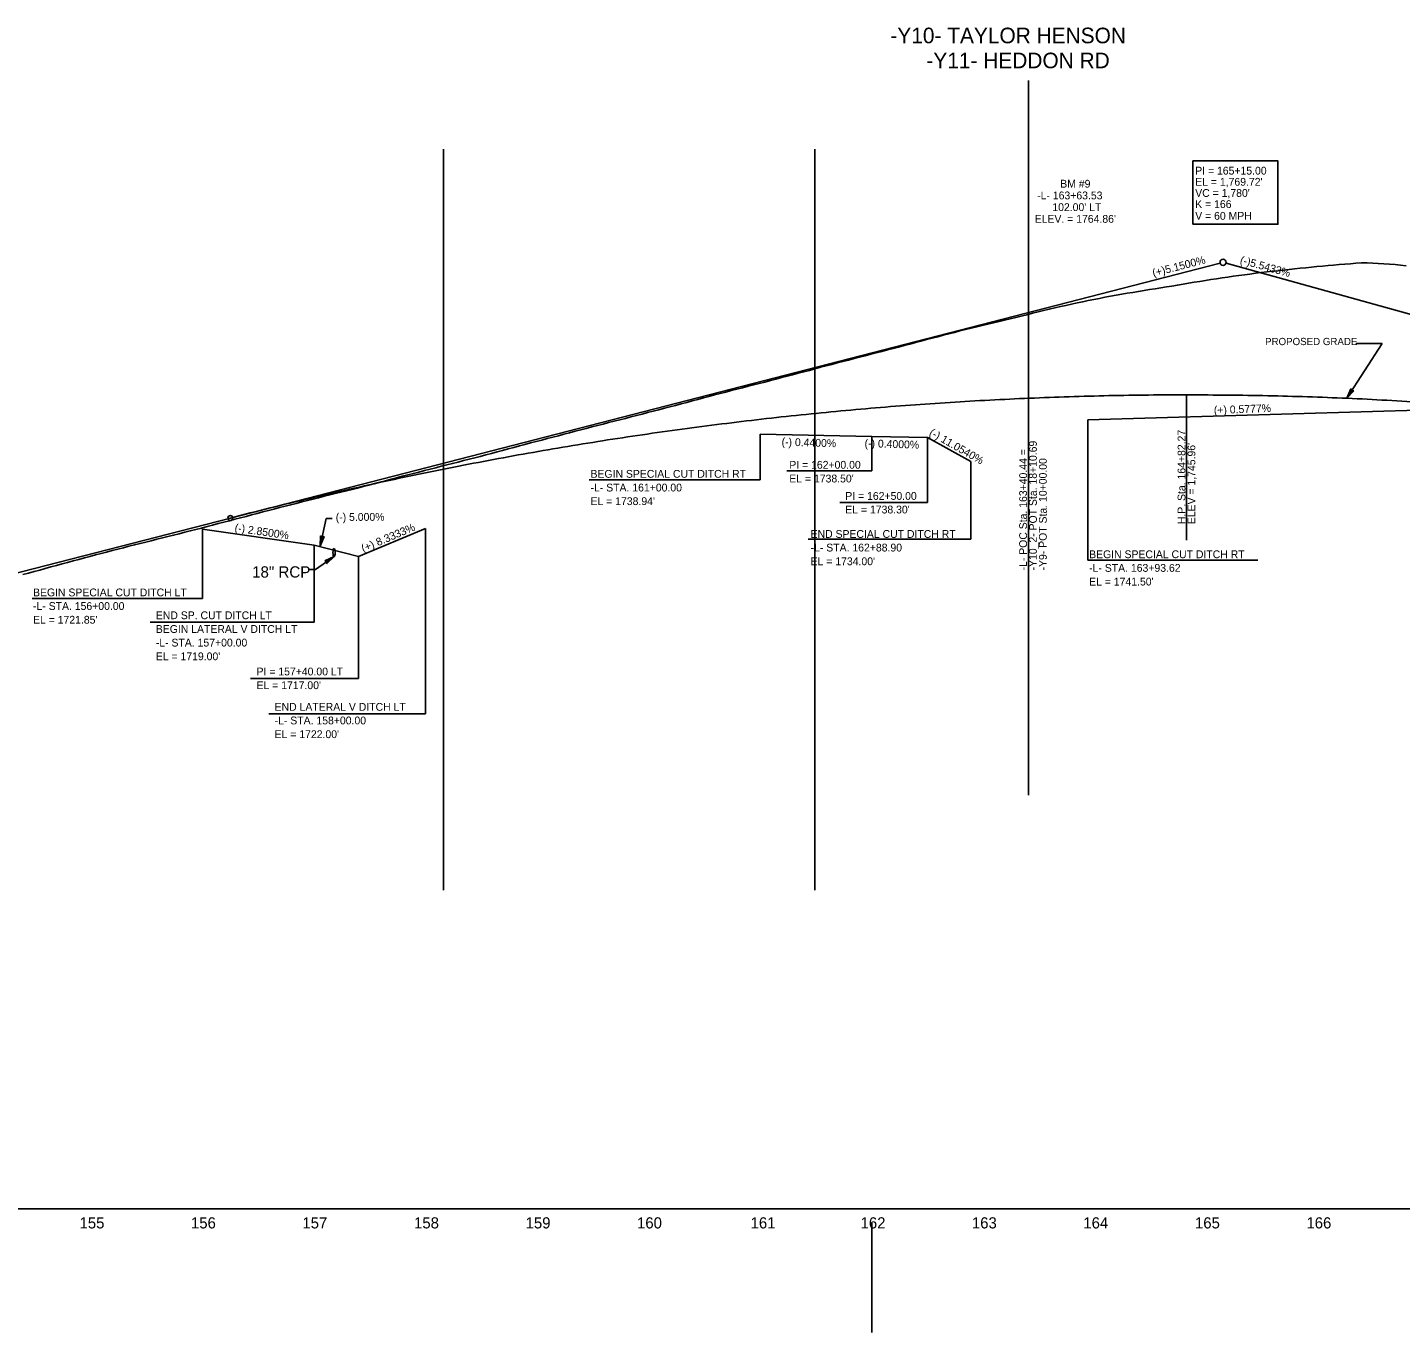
# Model space of a CAD drawing. Extents: x 498575 to 532350, y 405181 to 484585.
# Drawn here: x 520262 to 521493, y 483123 to 484293 of the extents above; entities that cross this region are included whole.
import ezdxf

# ---------------------------------------------------------------- set-up
doc = ezdxf.new("R2010")
doc.units = 0
for name, color, linetype in [('Exist Profile Cell', 7, 'Continuous'), ('Exist Vertical Profile Ground Line', 7, 'Continuous'), ('Exist Vertical Profile Horizontal Axis Label Major', 7, 'Continuous'), ('Prop Drainage Structure Pipe Welded Steel 54in Label', 7, 'Continuous'), ('Prop Grid Mask', 7, 'Continuous'), ('Prop PFL Text', 7, 'Continuous'), ('Prop Vertical Profile Curve Label', 7, 'Continuous'), ('Prop Vertical Profile Ditch Grade Left', 7, 'Continuous'), ('Prop Vertical Profile Ditch Grade Left Label', 7, 'Continuous'), ('Prop Vertical Profile Ditch Grade Right', 7, 'Continuous'), ('Prop Vertical Profile Ditch Grade Right Label', 7, 'Continuous'), ('Prop Vertical Profile Grade', 7, 'Continuous'), ('Prop Vertical Profile Grade Label', 7, 'Continuous'), ('Prop Vertical Profile Strip Grade', 7, 'Continuous'), ('Prop VPI Label', 7, 'Continuous'), ('Scratch_Level_2', 7, 'Continuous'), ('Scratch_Level_4', 7, 'Continuous'), ('Sheet Profile Grid Minor CELL', 7, 'Continuous')]:
    doc.layers.add(name, color=color, linetype=linetype)

msp = doc.modelspace()

# ---------------------------------------------------------------- linework, layer by layer
at = {"layer": 'Exist Profile Cell'}
msp.add_line((505856.7, 483233.7), (526056.7, 483233.7), dxfattribs=at)
at = {"layer": 'Exist Vertical Profile Ground Line'}
for points in [[(521313.2, 484065.2), (521318.2, 484066), (521323.2, 484066.9), (521328.2, 484067.6), (521333.2, 484068.4), (521338.2, 484069.1), (521343.2, 484069.8), (521348.2, 484070.4), (521353.2, 484071.1), (521358.2, 484071.8), (521363.2, 484072.5), (521368.2, 484073.1), (521373.2, 484073.7), (521378.2, 484074.3), (521383.2, 484074.8), (521388.2, 484075.3), (521393.2, 484075.9), (521398.2, 484076.5), (521403.2, 484077), (521408.2, 484077.5), (521413.2, 484078.1), (521418.2, 484078.6), (521423.2, 484079), (521428.2, 484079.5), (521433.2, 484079.9), (521438.2, 484080.4), (521443.2, 484080.8), (521448.2, 484081.1), (521453.2, 484081.5), (521458.2, 484081.8), (521463.2, 484081.8), (521468.2, 484081.6), (521473.2, 484081.4), (521478.2, 484081), (521483.2, 484080.7), (521488.2, 484080.3), (521493.2, 484079.8), (521498.2, 484079.3)], [(520813.2, 483946.3), (520818.2, 483947.6), (520823.2, 483948.8), (520828.2, 483950.1), (520833.2, 483951.5), (520838.2, 483952.8), (520843.2, 483954.1), (520848.2, 483955.4), (520853.2, 483956.8), (520858.2, 483958.1), (520863.2, 483959.5), (520868.2, 483960.8), (520873.2, 483962.1), (520878.2, 483963.4), (520883.2, 483964.7), (520888.2, 483966), (520893.2, 483967.3), (520898.2, 483968.6), (520903.2, 483969.9), (520908.2, 483971.2), (520913.2, 483972.4), (520918.2, 483973.7), (520923.2, 483975), (520928.2, 483976.4), (520933.2, 483977.7), (520938.2, 483979), (520943.2, 483980.3), (520948.2, 483981.6), (520953.2, 483982.9), (520958.2, 483984.2), (520963.2, 483985.5), (520968.2, 483986.8), (520973.2, 483988.2), (520978.2, 483989.5), (520983.2, 483990.8), (520988.2, 483992.1), (520993.2, 483993.4), (520998.2, 483994.7), (521003.2, 483996), (521008.2, 483997.3), (521013.2, 483998.5), (521018.2, 483999.9), (521023.2, 484001.2), (521028.2, 484002.5), (521033.2, 484003.8), (521038.2, 484005.1), (521043.2, 484006.4), (521048.2, 484007.7), (521053.2, 484009.1), (521058.2, 484010.4), (521063.2, 484011.7), (521068.2, 484013), (521073.2, 484014.3), (521078.2, 484015.6), (521083.2, 484017), (521088.2, 484018.2), (521093.2, 484019.5), (521098.2, 484020.8), (521103.2, 484022), (521108.2, 484023.2), (521113.2, 484024.5), (521118.2, 484025.7), (521123.2, 484026.9), (521128.2, 484028.1), (521133.2, 484029.3), (521138.2, 484030.5), (521143.2, 484031.8), (521148.2, 484033), (521153.2, 484034.2), (521158.2, 484035.4), (521163.2, 484036.7), (521168.2, 484037.9), (521173.2, 484039.2), (521178.2, 484040.3), (521183.2, 484041.5), (521188.2, 484042.6), (521193.2, 484043.7), (521198.2, 484044.8), (521203.2, 484045.9), (521208.2, 484047), (521213.2, 484048), (521218.2, 484049), (521223.2, 484050), (521228.2, 484051), (521233.2, 484051.9), (521238.2, 484052.8), (521243.2, 484053.7), (521248.2, 484054.6), (521253.2, 484055.4), (521258.2, 484056.3), (521263.2, 484057.1), (521268.2, 484057.9), (521273.2, 484058.7), (521278.2, 484059.5), (521283.2, 484060.3), (521288.2, 484061.1), (521293.2, 484062), (521298.2, 484062.8), (521303.2, 484063.6), (521308.2, 484064.4), (521313.2, 484065.2)], [(520313.2, 483817.3), (520318.2, 483818.7), (520323.2, 483820), (520328.2, 483821.3), (520333.2, 483822.6), (520338.2, 483823.9), (520343.2, 483825.2), (520348.2, 483826.5), (520353.2, 483827.8), (520358.2, 483829), (520363.2, 483830.3), (520368.2, 483831.5), (520373.2, 483832.7), (520378.2, 483834), (520383.2, 483835.2), (520388.2, 483836.5), (520393.2, 483837.7), (520398.2, 483839), (520403.2, 483840.3), (520408.2, 483841.5), (520413.2, 483842.8), (520418.2, 483844.1), (520423.2, 483845.4), (520428.2, 483846.8), (520433.2, 483848.1), (520438.2, 483849.4), (520443.2, 483850.7), (520448.2, 483852), (520453.2, 483853.3), (520458.2, 483854.6), (520463.2, 483855.9), (520468.2, 483857.2), (520473.2, 483858.5), (520478.2, 483859.8), (520483.2, 483861.1), (520488.2, 483862.4), (520493.2, 483863.7), (520498.2, 483865), (520503.2, 483866.2), (520508.2, 483867.5), (520513.2, 483868.8), (520518.2, 483870), (520523.2, 483871.3), (520528.2, 483872.6), (520533.2, 483873.8), (520538.2, 483875.1), (520543.2, 483876.3), (520548.2, 483877.5), (520553.2, 483878.8), (520558.2, 483880), (520563.2, 483881.3), (520568.2, 483882.5), (520573.2, 483883.9), (520578.2, 483885.2), (520583.2, 483886.5), (520588.2, 483887.9), (520593.2, 483889.2), (520598.2, 483890.5), (520603.2, 483891.8), (520608.2, 483893.1), (520613.2, 483894.3), (520618.2, 483895.6), (520623.2, 483896.9), (520628.2, 483898.2), (520633.2, 483899.5), (520638.2, 483900.8), (520643.2, 483902.1), (520648.2, 483903.3), (520653.2, 483904.6), (520658.2, 483905.9), (520663.2, 483907.1), (520668.2, 483908.4), (520673.2, 483909.7), (520678.2, 483911), (520683.2, 483912.4), (520688.2, 483913.7), (520693.2, 483915.1), (520698.2, 483916.4), (520703.2, 483917.8), (520708.2, 483919.1), (520713.2, 483920.4), (520718.2, 483921.6), (520723.2, 483922.9), (520728.2, 483924.3), (520733.2, 483925.6), (520738.2, 483926.9), (520743.2, 483928.2), (520748.2, 483929.5), (520753.2, 483930.9), (520758.2, 483932.2), (520763.2, 483933.5), (520768.2, 483934.8), (520773.2, 483936), (520778.2, 483937.3), (520783.2, 483938.6), (520788.2, 483939.9), (520793.2, 483941.1), (520798.2, 483942.4), (520803.2, 483943.7), (520808.2, 483945), (520813.2, 483946.3)], [(520258.2, 483802.5), (520263.2, 483803.8), (520268.2, 483805.1), (520273.2, 483806.5), (520278.2, 483807.8), (520283.2, 483809.2), (520288.2, 483810.6), (520293.2, 483811.9), (520298.2, 483813.3), (520303.2, 483814.7), (520308.2, 483816), (520313.2, 483817.3)]]:
    msp.add_lwpolyline(points, dxfattribs=at)
at = {"layer": 'Prop Drainage Structure Pipe Welded Steel 54in Label'}
for p in [(520537.1, 483818.7), (520514.3, 483806.9)]:
    msp.add_line(p, (520520.3, 483806.9), dxfattribs=at)
msp.add_lwpolyline([(520528.8, 483814.8), (520537.1, 483818.7), (520530.6, 483812.2), (520530.6, 483814.2)], close=True, dxfattribs=at)
msp.add_ellipse((520537.1, 483822.2), major_axis=(0, 3.5), ratio=0.285714, dxfattribs=at)
at = {"layer": 'Prop Grid Mask'}
msp.add_lwpolyline([(521307, 484116.4), (521383.2, 484116.4), (521383.2, 484173.2), (521307, 484173.2)], close=True, dxfattribs=at)
at = {"layer": 'Prop PFL Text'}
for p, q in [((521445.1, 483960.4), (521476.6, 484009.6)), ((521476.6, 484009.6), (521453.2, 484009.6))]:
    msp.add_line(p, q, dxfattribs=at)
msp.add_lwpolyline([(521451.2, 483967.2), (521445.1, 483960.4), (521448.6, 483968.9), (521449.3, 483967.1)], close=True, dxfattribs=at)
at = {"layer": 'Prop Vertical Profile Curve Label'}
msp.add_circle((520444.1, 483853.1), 2.25, dxfattribs=at)
at = {"layer": 'Prop Vertical Profile Ditch Grade Left'}
msp.add_lwpolyline([(520419.1, 483843), (520519.1, 483828.7), (520559.1, 483818.7), (520619.1, 483843.7), (520619.1, 483843.7)], dxfattribs=at)
at = {"layer": 'Prop Vertical Profile Ditch Grade Left Label'}
for p, q in [((520529.9, 483852.6), (520524.6, 483828)), ((520529.9, 483852.6), (520535.4, 483852.6)), ((520419.1, 483843), (520419.1, 483780.9)), ((520619.1, 483843.7), (520619.1, 483677.6)), ((520519.1, 483828.7), (520519.1, 483759.8)), ((520559.1, 483818.7), (520559.1, 483709.2)), ((520266.4, 483780.9), (520419.1, 483780.9)), ((520372.3, 483759.8), (520519.1, 483759.8)), ((520462.3, 483709.2), (520559.1, 483709.2)), ((520478.5, 483677.6), (520619.1, 483677.6))]:
    msp.add_line(p, q, dxfattribs=at)
msp.add_lwpolyline([(520525, 483837.2), (520524.6, 483828), (520528.1, 483836.5), (520526.3, 483835.8)], close=True, dxfattribs=at)
at = {"layer": 'Prop Vertical Profile Ditch Grade Right'}
for points in [[(521212.7, 483941.2), (521519.1, 483950.1)], [(520919.1, 483928.4), (521019.1, 483926.2), (521069.1, 483925.2), (521108, 483903.7)]]:
    msp.add_lwpolyline(points, dxfattribs=at)
at = {"layer": 'Prop Vertical Profile Ditch Grade Right Label'}
for p, q in [((521212.7, 483941.2), (521212.7, 483815.2)), ((520919.1, 483928.4), (520919.1, 483887.2)), ((521019.1, 483926.2), (521019.1, 483895.3)), ((521069.1, 483925.2), (521069.1, 483867.1)), ((521108, 483903.7), (521108, 483834)), ((520919.1, 483887.2), (520765.7, 483887.2)), ((521019.1, 483895.3), (520943, 483895.3)), ((521069.1, 483867.1), (520990.5, 483867.1)), ((521108, 483834), (520962.2, 483834)), ((521365.3, 483815.2), (521212.7, 483815.2))]:
    msp.add_line(p, q, dxfattribs=at)
at = {"layer": 'Prop Vertical Profile Grade'}
msp.add_line((520034.1, 483747.6), (520444.1, 483853.1), dxfattribs=at)
msp.add_spline([(520444.1, 483853.1), (520479.7, 483862.1), (520515.3, 483870.7), (520550.9, 483878.9), (520586.5, 483886.8), (520622.1, 483894.2), (520657.7, 483901.3), (520693.3, 483908), (520728.9, 483914.3), (520764.5, 483920.2), (520800.1, 483925.8), (520835.7, 483930.9), (520871.3, 483935.7), (520906.9, 483940.1), (520942.5, 483944.2), (520978.1, 483947.8), (521013.7, 483951.1), (521049.3, 483954), (521084.9, 483956.5), (521120.5, 483958.6), (521156.1, 483960.3), (521191.7, 483961.7), (521227.3, 483962.7), (521262.9, 483963.3), (521298.5, 483963.5), (521334.1, 483963.3), (521369.7, 483962.8), (521405.3, 483961.9), (521440.9, 483960.6), (521476.5, 483958.9), (521512.1, 483956.8), (521547.7, 483954.4), (521583.3, 483951.6), (521618.9, 483948.4), (521654.5, 483944.8), (521690.1, 483940.8), (521725.7, 483936.5), (521761.3, 483931.7), (521796.9, 483926.6), (521832.5, 483921.1), (521868.1, 483915.3), (521903.7, 483909), (521939.3, 483902.4), (521974.9, 483895.4), (522010.5, 483888), (522046.1, 483880.2), (522081.7, 483872.1), (522117.3, 483863.5), (522152.9, 483854.6), (522188.5, 483845.3), (522224.1, 483835.6)], degree=3, dxfattribs=at)
at = {"layer": 'Prop Vertical Profile Strip Grade'}
for p, q in [((521159.5, 483802.9), (521159.5, 483960.5)), ((521301.3, 483963.5), (521301.3, 483833.3))]:
    msp.add_line(p, q, dxfattribs=at)
at = {"layer": 'Prop VPI Label'}
for p, q in [((520444.1, 483853.1), (521331.4, 484081.6)), ((522224.1, 483835.6), (521336.7, 484081.6))]:
    msp.add_line(p, q, dxfattribs=at)
msp.add_circle((521334.1, 484082.3), 2.75, dxfattribs=at)
at = {"layer": 'Scratch_Level_2'}
msp.add_line((521159.5, 484245.4), (521159.5, 483604.7), dxfattribs=at)
at = {"layer": 'Scratch_Level_4'}
for p, q in [((520635.2, 484183.7), (520635.2, 483519.4)), ((520968.1, 484183.7), (520968.1, 483519.4))]:
    msp.add_line(p, q, dxfattribs=at)
at = {"layer": 'Sheet Profile Grid Minor CELL'}
msp.add_line((521019.1, 483221.2), (521019.1, 483122.9), dxfattribs=at)

# ---------------------------------------------------------------- texts
at = {"layer": 'Exist Vertical Profile Horizontal Axis Label Major'}
for s, p in [('155', (520308.9, 483216.2)), ('155', (520308.9, 483216.2)), ('156', (520408.8, 483216.2)), ('156', (520408.8, 483216.2)), ('157', (520508.7, 483216.2)), ('157', (520508.7, 483216.2)), ('158', (520608.8, 483216.2)), ('158', (520608.8, 483216.2)), ('159', (520708.8, 483216.2)), ('159', (520708.8, 483216.2)), ('160', (520808.7, 483216.2)), ('160', (520808.7, 483216.2)), ('161', (520910.5, 483216.2)), ('161', (520910.5, 483216.2)), ('162', (521009.1, 483216.2)), ('162', (521009.1, 483216.2)), ('163', (521108.9, 483216.2)), ('163', (521108.9, 483216.2)), ('164', (521208.8, 483216.2)), ('164', (521208.8, 483216.2)), ('165', (521308.9, 483216.2)), ('165', (521308.9, 483216.2)), ('166', (521408.8, 483216.2)), ('166', (521408.8, 483216.2))]:
    msp.add_text(s, height=10, dxfattribs=at).set_placement(p)
at = {"layer": 'Prop Drainage Structure Pipe Welded Steel 54in Label'}
msp.add_text('18" RCP', height=10.12, dxfattribs=at).set_placement((520463.6, 483799.7))
at = {"layer": 'Prop PFL Text'}
for s, height, p in [('BM #9', 7, (521188.1, 484149.3)), ('-L- 163+63.53', 7, (521167.4, 484138.8)), ("102.00' LT", 7, (521181, 484128.3)), ("ELEV. = 1764.86'", 7, (521165.2, 484117.8)), ('PROPOSED GRADE', 6.516, (521371.7, 484008.1))]:
    msp.add_text(s, height=height, dxfattribs=at).set_placement(p)
at = {"layer": 'Prop Vertical Profile Curve Label'}
for s, p in [("VC = 1,780'", (521309.1, 484141)), ('K = 166', (521309.1, 484131)), ('V = 60 MPH ', (521309.1, 484120.5))]:
    msp.add_text(s, height=7, dxfattribs=at).set_placement(p)
at = {"layer": 'Prop Vertical Profile Ditch Grade Left Label'}
for s, rotation, p in [('(-) 2.8500%', 351.5875, (520447.6, 483841.1)), ('(-) 5.000%', 0.4068, (520538.6, 483850.4)), ('(+) 8.3333%', 23.0927, (520563.3, 483822.2)), ('BEGIN SPECIAL CUT DITCH LT', 360, (520267.2, 483782.9)), ('-L- STA. 156+00.00', 360, (520267.2, 483770.7)), ("EL = 1721.85'", 360, (520267.2, 483758.4)), ('END SP. CUT DITCH LT', 360, (520377.3, 483762.4)), ('BEGIN LATERAL V DITCH LT', 360, (520377.3, 483750.1)), ('-L- STA. 157+00.00', 360, (520377.3, 483737.9)), ("EL = 1719.00'", 360, (520377.3, 483725.6)), ('PI = 157+40.00 LT', 360, (520467.6, 483712)), ("EL = 1717.00'", 360, (520467.6, 483699.7)), ('END LATERAL V DITCH LT', 360, (520483.8, 483680.3)), ('-L- STA. 158+00.00', 360, (520483.8, 483668.1)), ("EL = 1722.00'", 360, (520483.8, 483655.8))]:
    msp.add_text(s, height=7, rotation=rotation, dxfattribs=at).set_placement(p)
at = {"layer": 'Prop Vertical Profile Ditch Grade Right Label'}
for s, rotation, p in [('(+) 0.5777%', 2.1516, (521325.9, 483946.3)), ('(-) 0.4400%', 358.3146, (520938.2, 483918)), ('(-) 0.4000%', 358.3146, (521012.6, 483916.7)), ('(-) 11.0540%', 330.2143, (521070, 483927.7)), ('BEGIN SPECIAL CUT DITCH RT', 360, (520767, 483889.2)), ('PI = 162+00.00', 360, (520945.2, 483897.3)), ('-L- STA. 161+00.00', 360, (520767, 483876.9)), ("EL = 1738.50'", 360, (520945.2, 483885)), ("EL = 1738.94'", 360, (520767, 483864.7)), ('PI = 162+50.00', 360, (520995.4, 483869.4)), ("EL = 1738.30'", 360, (520995.4, 483857.2)), ('END SPECIAL CUT DITCH RT', 360, (520964.3, 483835.3)), ('-L- STA. 162+88.90', 360, (520964.3, 483823.1)), ('BEGIN SPECIAL CUT DITCH RT', 360, (521214, 483817.1)), ("EL = 1734.00'", 360, (520964.3, 483810.8)), ('-L- STA. 163+93.62', 360, (521214, 483804.9)), ("EL = 1741.50'", 360, (521214, 483792.6))]:
    msp.add_text(s, height=7, rotation=rotation, dxfattribs=at).set_placement(p)
at = {"layer": 'Prop Vertical Profile Grade Label'}
for s, rotation, p in [('(+)5.1500%', 14.44, (521271.7, 484069.3)), ('(-)5.5433%', 344.5085, (521348.7, 484081.4))]:
    msp.add_text(s, height=7, rotation=rotation, dxfattribs=at).set_placement(p)
at = {"layer": 'Prop Vertical Profile Strip Grade'}
for s, p in [('-Y10_2- POT Sta. 18+10.69', (521167.1, 483806.1)), ('H.P. Sta. 164+82.27', (521300.3, 483847.6)), ('-L- POC Sta. 163+40.44 = ', (521158.3, 483806.1)), ("ELEV = 1,745.96'", (521309.2, 483847.6)), ('-Y9- POT Sta. 10+00.00', (521176, 483806.1))]:
    msp.add_text(s, height=7, rotation=90, dxfattribs=at).set_placement(p)
at = {"layer": 'Prop VPI Label'}
for s, p in [('PI = 165+15.00', (521309.1, 484161)), ("EL = 1,769.72'", (521309.1, 484151))]:
    msp.add_text(s, height=7, dxfattribs=at).set_placement(p)
at = {"layer": 'Scratch_Level_2'}
for s, p in [('-Y10- TAYLOR HENSON ', (521035.8, 484278.7)), ('-Y11- HEDDON RD', (521068.1, 484256.3))]:
    msp.add_text(s, height=14, dxfattribs=at).set_placement(p)

doc.saveas('drawing.dxf')
